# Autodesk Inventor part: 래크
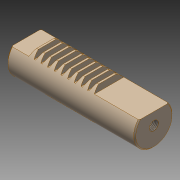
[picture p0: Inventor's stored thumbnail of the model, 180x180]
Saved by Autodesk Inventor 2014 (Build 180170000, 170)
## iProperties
Created: 2019-06
Part Number: 래크
Material: 스테인리스강
Document SubType Name: Modeling
Designer: mduedu
Density: 1 g/cm^3
Appearance: 기본값(1)
Author: mduedu
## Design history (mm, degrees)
sketch "스케치1"
  geometry: L1 (0, 0)-(120, 0); L2 (120, 0)-(120, 34); L3 (120, 34)-(0, 34); L4 (0, 34)-(0, 0)
  constraints: 8 end point, 2 parallel, 1 horizontal, 1 perpendicular
  dimensions: "d0" = 120 distance of L1.start L1.end; "d1" = 34 distance of L1.end L2.end
extrude "돌출1" new body sketch "스케치1" stored distance "d2" = 36; taper "d3" = 0 deg
sketch "스케치2"
  geometry: L1 (0, 0)-(120, 0) reference; L2 (120, 0)-(120, 34) reference; L3 (120, 34)-(0, 34) reference; L4 (0, 34)-(0, 0) reference; L5 (15.1, 29.5)-(16.42, 29.5); L6 (18.058, 34)-(13.462, 34); L7 (15.76, 34)-(15.76, 29.5); L8 (13.462, 34)-(15.1, 29.5); L9 (18.058, 34)-(16.42, 29.5); L10 (14.19, 32)-(17.33, 32); 1 further point
  constraints: 12 end point, 2 midpoint, 2 point on line, 1 collinear, 1 horizontal, 1 parallel, 1 perpendicular, 1 symmetric about line
  dimensions: "d4" = 20 deg angle of L9 L7; "d5" = 2 distance between parallel lines of L10 L6; "d7" = 4.5 distance between parallel lines of L5 L6 (= 2.25 x d5); "d8" = 3.14 distance of L10.start L10.end; "d9" = 15.76 distance between parallel lines of L4 L7
extrude "돌출2" cut sketch "스케치2" stored distance "d10" = 36; taper "d11" = 0 deg
sketch "스케치3"
  geometry: L1 (120, 34)-(80.858, 34) reference; L2 (68.298, 34)-(66.66, 29.5) reference; L3 (66.66, 29.5)-(65.34, 29.5) reference; L4 (65.34, 29.5)-(63.702, 34) reference; L5 (62.018, 34)-(60.38, 29.5) reference; L6 (60.38, 29.5)-(59.06, 29.5) reference; L7 (59.06, 29.5)-(57.422, 34) reference; L8 (57.422, 34)-(55.738, 34) reference; L9 (55.738, 34)-(54.1, 29.5) reference; L10 (54.1, 29.5)-(52.78, 29.5) reference; L11 (52.78, 29.5)-(51.142, 34) reference; L12 (51.142, 34)-(49.458, 34) reference; L13 (49.458, 34)-(47.82, 29.5) reference; L14 (47.82, 29.5)-(46.5, 29.5) reference; L15 (46.5, 29.5)-(44.862, 34) reference; L16 (44.862, 34)-(43.178, 34) reference; L17 (43.178, 34)-(41.54, 29.5) reference; L18 (41.54, 29.5)-(40.22, 29.5) reference; L19 (40.22, 29.5)-(38.582, 34) reference; L20 (38.582, 34)-(36.898, 34) reference; L21 (36.898, 34)-(35.26, 29.5) reference; L22 (35.26, 29.5)-(33.94, 29.5) reference; L23 (33.94, 29.5)-(32.302, 34) reference; L24 (32.302, 34)-(30.618, 34) reference; L25 (30.618, 34)-(28.98, 29.5) reference; L26 (28.98, 29.5)-(27.66, 29.5) reference; L27 (27.66, 29.5)-(26.022, 34) reference; L28 (26.022, 34)-(24.338, 34) reference; L29 (24.338, 34)-(22.7, 29.5) reference; L30 (22.7, 29.5)-(21.38, 29.5) reference; L31 (21.38, 29.5)-(19.742, 34) reference; L32 (19.742, 34)-(18.058, 34) reference; L33 (18.058, 34)-(16.42, 29.5) reference; L34 (16.42, 29.5)-(15.1, 29.5) reference; L35 (15.1, 29.5)-(13.462, 34) reference; L36 (0, 34)-(0, 0) reference; L37 (0, 0)-(120, 0) reference; L38 (120, 0)-(120, 34) reference; L39 (13.462, 34)-(0, 34) reference; L40 (80.858, 34)-(79.22, 29.5) reference; L41 (79.22, 29.5)-(77.9, 29.5) reference; L42 (77.9, 29.5)-(76.262, 34) reference; L43 (74.578, 34)-(72.94, 29.5) reference; L44 (72.94, 29.5)-(71.62, 29.5) reference; L45 (71.62, 29.5)-(69.982, 34) reference; L46 (69.982, 34)-(68.298, 34) reference; L47 (63.702, 34)-(62.018, 34) reference; L48 (76.262, 34)-(74.578, 34) reference; L49 (15.1, 29.5)-(0, 29.5); L50 (79.22, 29.5)-(120, 29.5); 1 further point
  constraints: 4 end point, 2 perpendicular, 2 point on line
extrude "돌출3" cut sketch "스케치3" stored distance "d18" = 36; taper "d19" = 0 deg
sketch "스케치4"
  geometry: L1 (0, 29.5)-(0, 0) reference; L2 (0, 0)-(120, 0) reference; L3 (120, 0)-(120, 29.5) reference; L4 (76.262, 34)-(74.578, 34) reference; L5 (68.298, 34)-(66.66, 29.5) reference; L6 (66.66, 29.5)-(65.34, 29.5) reference; L7 (65.34, 29.5)-(63.702, 34) reference; L8 (62.018, 34)-(60.38, 29.5) reference; L9 (60.38, 29.5)-(59.06, 29.5) reference; L10 (59.06, 29.5)-(57.422, 34) reference; L11 (57.422, 34)-(55.738, 34) reference; L12 (55.738, 34)-(54.1, 29.5) reference; L13 (54.1, 29.5)-(52.78, 29.5) reference; L14 (52.78, 29.5)-(51.142, 34) reference; L15 (51.142, 34)-(49.458, 34) reference; L16 (49.458, 34)-(47.82, 29.5) reference; L17 (47.82, 29.5)-(46.5, 29.5) reference; L18 (46.5, 29.5)-(44.862, 34) reference; L19 (44.862, 34)-(43.178, 34) reference; L20 (43.178, 34)-(41.54, 29.5) reference; L21 (41.54, 29.5)-(40.22, 29.5) reference; L22 (40.22, 29.5)-(38.582, 34) reference; L23 (38.582, 34)-(36.898, 34) reference; L24 (36.898, 34)-(35.26, 29.5) reference; L25 (35.26, 29.5)-(33.94, 29.5) reference; L26 (33.94, 29.5)-(32.302, 34) reference; L27 (32.302, 34)-(30.618, 34) reference; L28 (30.618, 34)-(28.98, 29.5) reference; L29 (28.98, 29.5)-(27.66, 29.5) reference; L30 (27.66, 29.5)-(26.022, 34) reference; L31 (26.022, 34)-(24.338, 34) reference; L32 (24.338, 34)-(22.7, 29.5) reference; L33 (22.7, 29.5)-(21.38, 29.5) reference; L34 (21.38, 29.5)-(19.742, 34) reference; L35 (19.742, 34)-(18.058, 34) reference; L36 (18.058, 34)-(16.42, 29.5) reference; L37 (16.42, 29.5)-(0, 29.5) reference; L38 (30, 0)-(76, 0); L39 (76, 0)-(76, 4); L40 (76, 4)-(30, 4); L41 (30, 4)-(30, 0); L42 (120, 29.5)-(77.9, 29.5) reference; L43 (77.9, 29.5)-(76.262, 34) reference; L44 (74.578, 34)-(72.94, 29.5) reference; L45 (72.94, 29.5)-(71.62, 29.5) reference; L46 (71.62, 29.5)-(69.982, 34) reference; L47 (69.982, 34)-(68.298, 34) reference; L48 (63.702, 34)-(62.018, 34) reference; 1 further point
  constraints: 8 end point, 2 parallel, 1 horizontal, 1 perpendicular, 1 point on line
  dimensions: "d20" = 30 distance between parallel lines of L41 L1; "d22" = 46 distance between parallel lines of L39 L41; "d23" = 4 distance between parallel lines of L2 L40
extrude "돌출4" cut sketch "스케치4" stored distance "d24" = 36; taper "d25" = 0 deg
sketch "스케치5"
  geometry: L1 (36, 0)-(0, 0) reference; C1 r 18 at (18, 18); 2 further points
  constraints: 1 centre point, 1 midpoint, 1 tangent, 1 vertical alignment
  dimensions: "d26" = 36 diameter of C1
extrude "돌출5" sketch "스케치5" stored distance "d27" = 36; taper "d28" = 0 deg
chamfer "모따기1" distance "d29" = 1; stored, may be unused: second distance "d30" = 2, angle "d31" = 45 deg
hole "구멍1" diameter "d34" = 8.647; stored, may be unused: countersink angle "d38" = 90 deg, drill point angle "d40" = 118 deg; dims "d32" = 10, "d33" = 10, "d35" = 20, "d36" = 4, "d37" = 2, "d39" = 22
node "솔리드1"
pattern_linear "직사각형 패턴1" dims "d14" = 6.28, "d17" = 6.28
node "투영된 루프1"
node "투영된 루프2"
node "투영된 루프3"
